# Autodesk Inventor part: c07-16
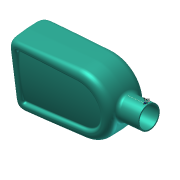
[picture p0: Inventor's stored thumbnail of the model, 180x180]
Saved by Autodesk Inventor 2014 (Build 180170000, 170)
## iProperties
Created: 2010-12
Part Number: c07-16
Material: Generic
Document SubType Name: Modeling
Designer: Beta-8540w
Density: 1 g/cm^3
Appearance: Smooth - Aqua
Author: Beta-8540w
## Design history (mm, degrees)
sketch "Sketch1"
  geometry: L1 (-25, 0)-(25, 0); L2 (25, 0)-(25, 80); L3 (25, 80)-(-25, 80); L4 (-25, 80)-(-25, 0); 2 further points
  constraints: 8 end point, 2 parallel, 1 coincident, 1 horizontal, 1 midpoint, 1 perpendicular
  dimensions: "d0" = 50 distance of L3.end L2.end; "d1" = 80 distance of L2.end L1.end
extrude "Extrusion1" new body sketch "Sketch1" distance "d2" = 15; taper "d3" = 0 deg
feature "FaceDraft1" dims angle "d4" = -2 deg
fillet "Fillet1"
fillet "Fillet2" dims "d5" = 8, "d6" = 8, "d7" = 8, "d8" = 8, "d9" = 8, "d10" = 8, "d11" = 3, "d12" = 3, "d13" = 3, "d14" = 6, "d15" = 5
sketch "Sketch2"
  geometry: L1 (5.522, 12)-(38.474, 12) reference; L2 (0, 0)-(43.996, 0) reference; L3 (41.757, 6.83)-(41.995, 0); L4 (41.925, 2)-(2.071, 2); L5 (2.001, 0)-(2.24, 6.83); L6 (5.522, 10)-(38.474, 10); A1 r 5.284 centre (38.474, 6.716) between (43.755, 6.9) and (38.474, 12) reference; A2 r 5.284 centre (5.522, 6.716) between (5.522, 12) and (0.241, 6.9) reference; A3 r 3.284 centre (38.474, 6.716) between (41.757, 6.83) and (38.474, 10); A4 r 3.284 centre (5.522, 6.716) between (5.522, 10) and (2.24, 6.83); 1 further point
  constraints: 8 end point, 4 point on circle, 4 point on line, 2 centre point, 1 other
  dimensions: "d16" = 2 radial gap between concentric circles of A2 A4
extrude "Extrusion2" cut sketch "Sketch2" distance "d17" = 1; taper "d18" = 0 deg
feature "FaceDraft2" dims angle "d19" = 15 deg
sketch "Sketch3" dims "d20" = 2.5
  geometry: L1 (16.476, 3)-(-16.476, 3) reference; L2 (16.476, 5.5)-(-16.476, 5.5); 9 further points
  constraints: 2 end point, 2 parallel, 1 horizontal alignment, 19 other
extrude "Extrusion3" cut sketch "Sketch3" distance "d21" = 3; taper "d22" = 0 deg
feature "FaceDraft3" dims angle "d23" = 10 deg
workplane "Work Plane1"
sketch "Sketch4"
  geometry: L1 (41.1, -1.222)-(41.476, -12) reference; L2 (41.476, -12)-(-8.524, -12) reference; L3 (-8.524, -12)-(-8.147, -1.222) reference; L4 (-3.776, 3)-(-1.272, 3) reference; L5 (-0.743, 0)-(33.695, 0) reference; L6 (34.225, 3)-(36.728, 3) reference; L7 (-11.024, -1.856)-(43.976, -1.856); A1 r 100 centre (16.476, -98) between (43.976, -1.856) and (-11.024, -1.856); 2 further points
  constraints: 2 end point, 2 point on circle, 1 centre point, 1 midpoint, 1 parallel, 1 vertical alignment, 4 other
  dimensions: "d25" = 100 radius of A1; "d26" = 14 distance edge to line of A1 L2; "d27" = 55 distance of L7.start L7.end
extrude_surface "ExtrusionSrf1" sketch "Sketch4" dims "d28" = 86, "d29" = 0
feature "Replace Face1"
fillet "Fillet3" dims "d34" = 1, "d35" = 2
mirror "Mirror1"
fillet "Fillet4" dims "d36" = 20
workplane "Work Plane3"
sketch "Sketch6"
  geometry: C1 r 9 at (0, 0); 1 further point
  constraints: 1 centre point, 1 coincident
  dimensions: "d38" = 18 diameter of C1
extrude "Top Boss" join sketch "Sketch6" distance "d39" = 16; taper "d40" = 0 deg
fillet "Fillet5" dims "d41" = 3
shell "Shell1" dims "d44" = 1
sketch "Sketch7"
  geometry: L1 (-9, 80.285)-(-9, 96) reference; C1 r 0.75 at (-9, 94); 1 further point
  constraints: 1 centre point, 1 point on line
  dimensions: "d42" = 2 distance of L1.end C1.centre; "d43" = 1.5 diameter of C1
body "Solid1"
body "Srf1"
node "Project Cut Edges1"
